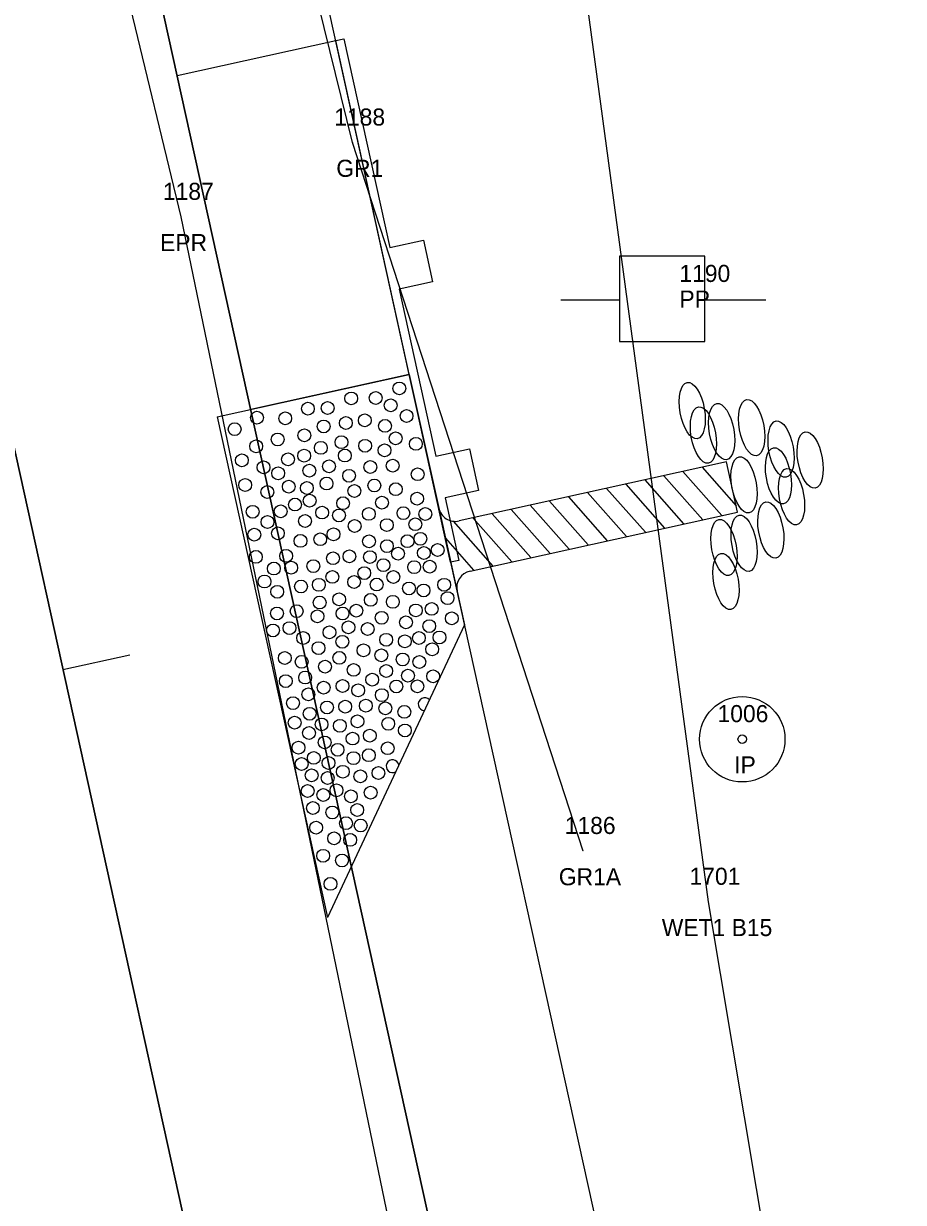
# Model space of a CAD drawing. Extents: x 2521558 to 2524785, y 882711 to 887632.
# Drawn here: x 2523808.4 to 2523859.8, y 884993.3 to 885062.2 of the extents above; entities that cross this region are included whole.
import ezdxf

# ---------------------------------------------------------------- set-up
doc = ezdxf.new("R2010")
doc.units = 0
for name, color, linetype in [('RD_EV_JurisArea', 7, 'Continuous'), ('RD_EX_DV_Prop_txCode', 7, 'Continuous'), ('RD_EX_DV_PropPin', 7, 'Continuous'), ('RD_EX_GuardRail', 7, 'Continuous'), ('RD_EX_GuardRail_txCode', 7, 'Continuous'), ('RD_EX_H2O_WetLd_txCode', 7, 'Continuous'), ('RD_EX_Road', 7, 'Continuous'), ('RD_EX_Road_txCode', 7, 'Continuous'), ('RD_EX_UT', 7, 'Continuous'), ('RD_EX_UT_txCode', 7, 'Continuous'), ('RD_HC_Cl', 7, 'Continuous'), ('RD_HC_Data_Tic', 7, 'Continuous'), ('RD_PD_Bridge', 7, 'Continuous'), ('RD_PD_Final_TrvlWay', 7, 'Continuous'), ('RD_PD_GR', 7, 'Continuous'), ('RD_PD_PaveShd', 7, 'Continuous'), ('RD_PD_SuperShp1', 7, 'Continuous'), ('RD_SMD_Locator', 7, 'Continuous')]:
    doc.layers.add(name, color=color, linetype=linetype)

# ---------------------------------------------------------------- blocks, each defined once
blk = doc.blocks.new('TBC1')
at = {"layer": 'RD_PD_GR'}
blk.add_lwpolyline([(12.5, 2.5), (15, 2.5), (15, 0.492), (25, 0.492), (25, 2.5), (27.5, 2.5), (27.5, 0.492), (31.25, 0.492), (31.25, 0), (0, 0), (0, 0.492), (12.5, 0.492)], close=True, dxfattribs=at)

msp = doc.modelspace()

# ---------------------------------------------------------------- linework, layer by layer
at = {"layer": 'RD_EV_JurisArea'}
msp.add_lwpolyline([(2523944.864, 884550.08), (2523910.413, 884709.577), (2523888.007, 884815.03), (2523863.93, 884918.366), (2523848.427, 885010.841), (2523837.066, 885095.132), (2523817.825, 885104.474)], dxfattribs=at)
at = {"layer": 'RD_EX_DV_PropPin'}
for centre, radius in [((2523850.412, 885020.357), 2.499), ((2523850.412, 885020.358), 0.25)]:
    msp.add_circle(centre, radius, dxfattribs=at)
at = {"layer": 'RD_EX_GuardRail'}
msp.add_lwpolyline([(2523841.112, 885013.814), (2523827.604, 885055.265), (2523819.275, 885089.086)], dxfattribs=at)
at = {"layer": 'RD_EX_Road'}
for p, q in [((2523817.578, 885050.917), (2523809.375, 885084.881)), ((2523837.97, 884952.456), (2523817.578, 885050.917))]:
    msp.add_line(p, q, dxfattribs=at)
at = {"layer": 'RD_EX_UT'}
for p, q in [((2523848.225, 885048.623), (2523843.225, 885048.623)), ((2523843.225, 885048.623), (2523843.225, 885043.623)), ((2523848.225, 885043.623), (2523848.225, 885048.623)), ((2523839.793, 885046.061), (2523843.263, 885046.061)), ((2523848.153, 885046.061), (2523851.793, 885046.061)), ((2523843.225, 885043.623), (2523848.225, 885043.623))]:
    msp.add_line(p, q, dxfattribs=at)
at = {"layer": 'RD_HC_Cl'}
msp.add_line((2523641.165, 885794.201), (2524197.759, 883266.557), dxfattribs=at)
at = {"layer": 'RD_HC_Data_Tic'}
msp.add_line((2523810.669, 885024.44), (2523814.575, 885025.3), dxfattribs=at)
at = {"layer": 'RD_PD_Bridge'}
for p, q in [((2523817.352, 885059.192), (2523826.629, 885061.235)), ((2523830.93, 885041.703), (2523821.653, 885039.66))]:
    msp.add_line(p, q, dxfattribs=at)
for points in [[(2523830.93, 885041.703), (2523794.372, 885207.726)], [(2523817.352, 885059.192), (2523826.629, 885061.235)]]:
    msp.add_lwpolyline(points, dxfattribs=at)
at = {"layer": 'RD_PD_Final_TrvlWay'}
msp.add_line((2523724.343, 885481.571), (2524039.392, 884050.847), dxfattribs=at)
at = {"layer": 'RD_PD_GR'}
msp.add_line((2523833.35, 885030.716), (2523900.015, 884727.969), dxfattribs=at)
at = {"layer": 'RD_PD_PaveShd'}
for p, q in [((2523819.699, 885039.23), (2523830.93, 885041.703)), ((2523832.866, 885032.914), (2523830.93, 885041.703)), ((2523830.93, 885041.703), (2523832.866, 885032.914)), ((2523819.699, 885039.23), (2523826.151, 885009.932)), ((2523849.487, 885036.583), (2523833.843, 885033.129)), ((2523850.134, 885033.653), (2523849.487, 885036.583)), ((2523850.134, 885033.653), (2523849.487, 885036.583)), ((2523845.826, 885035.775), (2523848.1, 885033.204)), ((2523845.826, 885035.775), (2523848.1, 885033.204)), ((2523846.943, 885036.021), (2523849.217, 885033.451)), ((2523846.943, 885036.021), (2523849.217, 885033.451)), ((2523848.06, 885036.268), (2523850.054, 885034.014)), ((2523848.06, 885036.268), (2523850.054, 885034.014)), ((2523842.475, 885035.035), (2523844.749, 885032.465)), ((2523842.475, 885035.035), (2523844.749, 885032.465)), ((2523843.592, 885035.282), (2523845.866, 885032.711)), ((2523843.592, 885035.282), (2523845.866, 885032.711)), ((2523844.709, 885035.528), (2523846.983, 885032.958)), ((2523844.709, 885035.528), (2523846.983, 885032.958)), ((2523839.124, 885034.295), (2523841.398, 885031.725)), ((2523839.124, 885034.295), (2523841.398, 885031.725)), ((2523840.241, 885034.542), (2523842.515, 885031.972)), ((2523840.241, 885034.542), (2523842.515, 885031.972)), ((2523841.358, 885034.788), (2523843.632, 885032.218)), ((2523841.358, 885034.788), (2523843.632, 885032.218)), ((2523834.487, 885030.199), (2523850.134, 885033.653)), ((2523835.773, 885033.556), (2523838.047, 885030.985)), ((2523835.773, 885033.556), (2523838.047, 885030.985)), ((2523836.89, 885033.802), (2523839.164, 885031.232)), ((2523836.89, 885033.802), (2523839.164, 885031.232)), ((2523838.007, 885034.049), (2523840.281, 885031.478)), ((2523838.007, 885034.049), (2523840.281, 885031.478)), ((2523832.866, 885032.914), (2523833.511, 885029.984)), ((2523833.492, 885033.115), (2523835.813, 885030.492)), ((2523834.656, 885033.309), (2523836.93, 885030.739)), ((2523834.656, 885033.309), (2523836.93, 885030.739)), ((2523833.042, 885032.115), (2523834.696, 885030.246)), ((2523833.08, 885031.943), (2523833.08, 885031.943)), ((2523833.511, 885029.984), (2523834.156, 885027.054)), ((2523834.156, 885027.054), (2523826.151, 885009.932))]:
    msp.add_line(p, q, dxfattribs=at)
for centre in [(2523830.349, 885040.885), (2523830.349, 885040.885), (2523827.534, 885040.3), (2523827.534, 885040.3), (2523828.967, 885040.325), (2523828.967, 885040.325), (2523828.967, 885040.325), (2523824.999, 885039.698), (2523824.999, 885039.698), (2523826.153, 885039.739), (2523826.153, 885039.739), (2523829.845, 885039.899), (2523822.02, 885039.178), (2523822.02, 885039.178), (2523823.673, 885039.133), (2523823.673, 885039.133), (2523827.222, 885038.86), (2523827.222, 885038.86), (2523828.326, 885039.017), (2523828.326, 885039.017), (2523829.513, 885038.692), (2523829.513, 885038.692), (2523830.772, 885039.275), (2523830.772, 885039.275), (2523820.715, 885038.501), (2523820.715, 885038.501), (2523824.791, 885038.139), (2523824.791, 885038.139), (2523825.918, 885038.659), (2523825.918, 885038.659), (2523821.973, 885037.498), (2523821.973, 885037.498), (2523823.233, 885037.898), (2523823.233, 885037.898), (2523825.757, 885037.407), (2523825.757, 885037.407), (2523826.962, 885037.739), (2523826.962, 885037.739), (2523828.347, 885037.529), (2523828.347, 885037.529), (2523830.13, 885037.967), (2523830.13, 885037.967), (2523831.317, 885037.642), (2523831.317, 885037.642), (2523821.137, 885036.679), (2523821.137, 885036.679), (2523823.836, 885036.738), (2523823.836, 885036.738), (2523824.78, 885036.947), (2523824.78, 885036.947), (2523827.161, 885036.956), (2523827.161, 885036.956), (2523829.482, 885037.263), (2523829.482, 885037.263), (2523822.403, 885036.265), (2523822.403, 885036.265), (2523823.257, 885035.918), (2523823.257, 885035.918), (2523825.086, 885036.073), (2523825.086, 885036.073), (2523826.234, 885036.326), (2523826.234, 885036.326), (2523828.647, 885036.286), (2523828.647, 885036.286), (2523829.96, 885036.364), (2523829.96, 885036.364), (2523821.33, 885035.236), (2523821.33, 885035.236), (2523826.089, 885035.32), (2523826.089, 885035.32), (2523827.408, 885035.773), (2523827.408, 885035.773), (2523831.42, 885035.863), (2523831.42, 885035.863), (2523822.624, 885034.82), (2523822.624, 885034.82), (2523823.878, 885035.137), (2523823.878, 885035.137), (2523824.938, 885035.058), (2523827.719, 885034.884), (2523827.719, 885034.884), (2523828.889, 885035.205), (2523828.889, 885035.205), (2523830.139, 885034.988), (2523830.139, 885034.988), (2523824.24, 885034.09), (2523824.24, 885034.09), (2523825.101, 885034.315), (2523825.101, 885034.315), (2523827.057, 885034.167), (2523827.057, 885034.167), (2523829.333, 885034.196), (2523829.333, 885034.196), (2523831.389, 885034.434), (2523831.389, 885034.434), (2523821.767, 885033.666), (2523821.767, 885033.666), (2523823.407, 885033.689), (2523823.407, 885033.689), (2523825.83, 885033.62), (2523825.83, 885033.62), (2523826.817, 885033.452), (2523826.817, 885033.452), (2523828.563, 885033.542), (2523828.563, 885033.542), (2523830.587, 885033.586), (2523830.587, 885033.586), (2523831.867, 885033.535), (2523831.867, 885033.535), (2523822.633, 885033.066), (2523822.633, 885033.066), (2523824.832, 885033.125), (2523824.832, 885033.125), (2523827.734, 885032.835), (2523827.734, 885032.835), (2523829.618, 885032.888), (2523829.618, 885032.888), (2523831.282, 885032.938), (2523821.864, 885032.324), (2523821.864, 885032.324), (2523823.244, 885032.408), (2523823.244, 885032.408), (2523824.564, 885031.963), (2523824.564, 885031.963), (2523825.721, 885032.06), (2523825.721, 885032.06), (2523826.497, 885032.349), (2523826.497, 885032.349), (2523828.577, 885031.941), (2523828.577, 885031.941), (2523830.823, 885031.944), (2523830.823, 885031.944), (2523831.582, 885032.085), (2523831.582, 885032.085), (2523823.725, 885031.088), (2523823.725, 885031.088), (2523829.621, 885031.656), (2523829.621, 885031.656), (2523830.274, 885031.22), (2523830.274, 885031.22), (2523831.784, 885031.259), (2523831.784, 885031.259), (2523832.587, 885031.427), (2523832.587, 885031.427), (2523821.953, 885031.028), (2523821.953, 885031.028), (2523824.02, 885030.397), (2523824.02, 885030.397), (2523825.316, 885030.486), (2523825.316, 885030.486), (2523826.467, 885030.948), (2523826.467, 885030.948), (2523827.428, 885031.058), (2523827.428, 885031.058), (2523828.627, 885031.016), (2523828.627, 885031.016), (2523829.418, 885030.543), (2523829.418, 885030.543), (2523831.214, 885030.426), (2523831.214, 885030.426), (2523832.127, 885030.452), (2523832.127, 885030.452), (2523823.006, 885030.346), (2523823.006, 885030.346), (2523826.429, 885029.856), (2523826.429, 885029.856), (2523828.295, 885030.079), (2523828.295, 885030.079), (2523830.001, 885029.855), (2523830.001, 885029.855), (2523822.459, 885029.586), (2523824.598, 885029.295), (2523824.598, 885029.295), (2523825.639, 885029.394), (2523825.639, 885029.394), (2523827.701, 885029.554), (2523827.701, 885029.554), (2523829.019, 885029.41), (2523829.019, 885029.41), (2523830.914, 885029.182), (2523830.914, 885029.182), (2523831.766, 885029.063), (2523831.766, 885029.063), (2523832.97, 885029.396), (2523832.97, 885029.396), (2523823.203, 885028.987), (2523823.203, 885028.987), (2523825.691, 885028.358), (2523825.691, 885028.358), (2523826.825, 885028.541), (2523826.825, 885028.541), (2523828.676, 885028.512), (2523828.676, 885028.512), (2523829.968, 885028.398), (2523829.968, 885028.398), (2523833.17, 885028.613), (2523833.17, 885028.613), (2523823.189, 885027.719), (2523823.189, 885027.719), (2523824.341, 885027.852), (2523824.341, 885027.852), (2523827.027, 885027.715), (2523827.027, 885027.715), (2523827.831, 885027.884), (2523827.831, 885027.884), (2523831.312, 885027.895), (2523831.312, 885027.895), (2523832.243, 885027.983), (2523832.243, 885027.983), (2523825.558, 885027.553), (2523825.558, 885027.553), (2523829.314, 885027.463), (2523829.314, 885027.463), (2523830.736, 885027.201), (2523830.736, 885027.201), (2523832.098, 885026.977), (2523832.098, 885026.977), (2523832.098, 885026.977), (2523833.417, 885027.43), (2523833.417, 885027.43), (2523822.96, 885026.723), (2523822.96, 885026.723), (2523823.922, 885026.86), (2523823.922, 885026.86), (2523824.722, 885026.285), (2523824.722, 885026.285), (2523826.258, 885026.612), (2523826.258, 885026.612), (2523827.371, 885026.909), (2523827.371, 885026.909), (2523828.495, 885026.805), (2523828.495, 885026.805), (2523831.494, 885026.285), (2523831.494, 885026.285), (2523832.697, 885026.313), (2523825.619, 885025.69), (2523825.619, 885025.69), (2523827.01, 885026.061), (2523827.01, 885026.061), (2523829.579, 885026.177), (2523829.579, 885026.177), (2523830.668, 885026.083), (2523830.668, 885026.083), (2523832.268, 885025.62), (2523832.268, 885025.62), (2523823.647, 885025.109), (2523823.647, 885025.109), (2523824.637, 885024.887), (2523824.637, 885024.887), (2523826.84, 885025.117), (2523826.84, 885025.117), (2523828.25, 885025.557), (2523828.25, 885025.557), (2523829.299, 885025.269), (2523829.299, 885025.269), (2523830.547, 885025.024), (2523830.547, 885025.024), (2523831.521, 885024.88), (2523831.521, 885024.88), (2523826.002, 885024.601), (2523826.002, 885024.601), (2523827.675, 885024.414), (2523827.675, 885024.414), (2523829.58, 885024.354), (2523829.58, 885024.354), (2523823.705, 885023.759), (2523823.705, 885023.759), (2523824.84, 885023.97), (2523824.84, 885023.97), (2523828.762, 885023.842), (2523828.762, 885023.842), (2523830.854, 885024.079), (2523830.854, 885024.079), (2523832.325, 885024.042), (2523825.026, 885022.984), (2523825.026, 885022.984), (2523825.92, 885023.378), (2523825.92, 885023.378), (2523827.027, 885023.472), (2523827.027, 885023.472), (2523827.938, 885023.219), (2523827.938, 885023.219), (2523829.325, 885022.938), (2523829.325, 885022.938), (2523830.17, 885023.448), (2523830.17, 885023.448), (2523831.406, 885023.456), (2523831.406, 885023.456), (2523824.131, 885022.47), (2523824.131, 885022.47), (2523826.119, 885022.219), (2523826.119, 885022.219), (2523827.181, 885022.266), (2523827.181, 885022.266), (2523828.389, 885022.322), (2523828.389, 885022.322), (2523829.53, 885022.168), (2523829.53, 885022.168), (2523825.102, 885021.848), (2523825.102, 885021.848), (2523830.64, 885021.96), (2523830.64, 885021.96), (2523824.22, 885021.325), (2523824.22, 885021.325), (2523825.799, 885021.225), (2523825.799, 885021.225), (2523826.869, 885021.144), (2523826.869, 885021.144), (2523827.898, 885021.404), (2523827.898, 885021.404), (2523829.699, 885021.26), (2523829.699, 885021.26), (2523830.672, 885020.872), (2523825.063, 885020.725), (2523825.063, 885020.725), (2523825.975, 885020.172), (2523825.975, 885020.172), (2523827.612, 885020.396), (2523827.612, 885020.396), (2523828.618, 885020.568), (2523828.618, 885020.568), (2523824.449, 885019.865), (2523824.449, 885019.865), (2523826.735, 885019.741), (2523826.735, 885019.741), (2523828.563, 885019.424), (2523828.563, 885019.424), (2523829.668, 885019.831), (2523829.668, 885019.831), (2523824.631, 885018.908), (2523824.631, 885018.908), (2523825.343, 885019.265), (2523825.343, 885019.265), (2523826.207, 885018.972), (2523826.207, 885018.972), (2523827.668, 885019.251), (2523827.668, 885019.251), (2523825.216, 885018.247), (2523825.216, 885018.247), (2523826.153, 885018.093), (2523826.153, 885018.093), (2523827.041, 885018.456), (2523827.041, 885018.456), (2523828.067, 885018.184), (2523828.067, 885018.184), (2523829.124, 885018.379), (2523829.124, 885018.379), (2523824.984, 885017.331), (2523824.984, 885017.331), (2523826.67, 885017.372), (2523826.67, 885017.372), (2523825.9, 885017.099), (2523825.9, 885017.099), (2523827.515, 885017.016), (2523827.515, 885017.016), (2523828.667, 885017.234), (2523828.667, 885017.234), (2523825.292, 885016.334), (2523825.292, 885016.334), (2523826.43, 885016.072), (2523826.43, 885016.072), (2523827.885, 885016.22), (2523827.226, 885015.446), (2523827.226, 885015.446), (2523828.085, 885015.311), (2523825.478, 885015.184), (2523825.478, 885015.184), (2523826.53, 885014.559), (2523826.53, 885014.559), (2523827.471, 885014.469), (2523827.471, 885014.469), (2523825.89, 885013.54), (2523825.89, 885013.54), (2523826.996, 885013.264), (2523826.996, 885013.264), (2523826.319, 885011.894), (2523826.319, 885011.894)]:
    msp.add_circle(centre, 0.375, dxfattribs=at)
for centre, radius, start, end in [((2523833.627, 885034.106), 1, 192.41848, 282.4481), ((2523834.703, 885029.223), 1, 102.4481, 192.41848), ((2523831.832, 885022.414), 0.375, 42.98701, 266.8976), ((2523829.956, 885018.778), 0.375, 11.79981, 298.0848)]:
    msp.add_arc(centre, radius, start, end, dxfattribs=at)
for centre in [(2523847.484, 885039.588), (2523847.484, 885039.588), (2523848.138, 885038.158), (2523848.138, 885038.158), (2523849.206, 885038.36), (2523849.206, 885038.36), (2523850.961, 885038.589), (2523850.961, 885038.589), (2523852.682, 885037.334), (2523852.682, 885037.334), (2523854.384, 885036.696), (2523854.384, 885036.696), (2523852.53, 885035.772), (2523852.53, 885035.772), (2523850.517, 885035.244), (2523850.517, 885035.244), (2523853.297, 885034.546), (2523853.297, 885034.546), (2523852.083, 885032.6), (2523852.083, 885032.6), (2523850.519, 885031.826), (2523850.519, 885031.826), (2523849.34, 885031.575), (2523849.456, 885029.59)]:
    msp.add_ellipse(centre, major_axis=(0.292, -1.645), ratio=0.429445, dxfattribs=at)
at = {"layer": 'RD_PD_SuperShp1'}
for p, q in [((2524039.392, 884050.847), (2523724.343, 885481.571)), ((2524025.719, 884047.837), (2523710.67, 885478.56)), ((2523710.67, 885478.56), (2524025.719, 884047.837))]:
    msp.add_line(p, q, dxfattribs=at)
at = {"layer": 'RD_SMD_Locator'}
for centre in [(2523827.604, 885055.265), (2523817.578, 885050.917), (2523841.112, 885013.814), (2523848.427, 885010.841)]:
    msp.add_circle(centre, 0.001, dxfattribs=at)

# ---------------------------------------------------------------- block references
at = {"layer": 'RD_PD_Bridge', "rotation": -77.58151740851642}
msp.add_blockref('TBC1', (2523826.629, 885061.235), dxfattribs=at)

# ---------------------------------------------------------------- texts
at = {"layer": 'RD_EX_DV_Prop_txCode'}
for s, p in [('1006', (2523848.964, 885021.358)), ('IP', (2523849.94, 885018.358))]:
    msp.add_text(s, height=1, dxfattribs=at).set_placement(p)
at = {"layer": 'RD_EX_GuardRail_txCode'}
for s, p in [('1188', (2523826.541, 885056.265)), ('GR1', (2523826.659, 885053.265)), ('1186', (2523840.026, 885014.814)), ('GR1A', (2523839.679, 885011.814))]:
    msp.add_text(s, height=1, dxfattribs=at).set_placement(p)
at = {"layer": 'RD_EX_H2O_WetLd_txCode'}
for s, p in [('1701', (2523847.325, 885011.841)), ('WET1 B15', (2523845.703, 885008.841))]:
    msp.add_text(s, height=1, dxfattribs=at).set_placement(p)
at = {"layer": 'RD_EX_Road_txCode'}
for s, p in [('1187', (2523816.515, 885051.917)), ('EPR', (2523816.35, 885048.917))]:
    msp.add_text(s, height=1, dxfattribs=at).set_placement(p)
at = {"layer": 'RD_EX_UT_txCode'}
for s, p in [('1190', (2523846.734, 885047.114)), ('PP', (2523846.734, 885045.614))]:
    msp.add_text(s, height=1, dxfattribs=at).set_placement(p)

doc.saveas('drawing.dxf')
